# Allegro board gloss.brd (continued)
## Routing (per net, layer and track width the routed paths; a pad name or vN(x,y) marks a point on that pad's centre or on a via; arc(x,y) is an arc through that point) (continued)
MEMORY.RA9: length 273.9
  TOP w0.15: U23.22 110.67,115.61 111.47,116.41 112.34,116.41 112.58,116.16 112.58,114.14 112.47,114.03 112.47,106.97 ; v1(116.34,71.61) 111.86,71.61 111.24,72.23 107.78,72.23 106.13,73.88 106.13,75.06 106.23,75.16 106.23,77.25 106.39,77.41 109.88,77.41 110.67,76.61 U20.22 ; 112.47,106.97 115.75,106.97 v1(116.49,107.7) 117.26,107.7 118.28,106.68 118.28,91.57 117.14,90.43 115.74,90.43 115.47,90.7 110.89,90.7 110.67,90.48 U21.22 ; 112.47,106.97 112.58,106.85 112.58,101.28 112.26,100.95 111.28,100.95 110.67,101.56 U22.22 ; v1(86.46,87.01) 85.89,87.58 85.89,87.77 86.67,88.56 U17.22 86.67,90.48 86.45,90.7 81.96,90.7 80.96,91.71 80.96,93.86 81.08,93.97 81.08,95.95 86.67,101.56 U18.22 86.46,102.43 v1(86.46,103.84) ; v1(88.28,74.6) 87.03,74.6 86.67,74.95 U16.22 ; U19.22 v1(86.67,111.97) ; U5.65 v1(68.91,102.77)
  BOTTOM w0.15: v1(116.49,107.7) 116.49,98.77 116.08,98.36 116.08,90.16 116.92,89.32 116.92,84.9 116.64,84.62 116.64,72.73 116.34,72.43 v1(116.34,71.61) 116.34,64.61 113.8,62.07 76.05,62.07 71.99,66.13 71.99,66.65 72.5,67.16 93.19,67.16 93.82,67.79 93.82,69.43 91.66,71.59 91.29,71.59 v1(88.28,74.6) 89.2,75.52 89.2,85.86 88.06,87.01 v1(86.46,87.01) ; v1(86.67,111.97) 86.67,111.15 87.19,110.63 87.19,104.57 v1(86.46,103.84) 84.86,103.84 80.89,99.87 71.81,99.87 v1(68.91,102.77)
MEMORY.RA10: length 199.7
  TOP w0.15: 111.42,109.47 111.94,109.99 U23.21 ; 111.42,109.47 111.12,109.77 99.79,109.77 99.56,109.99 v1(98.75,109.99) ; 111.42,109.47 v1(111.42,107.4) 111.42,104.59 111.94,104.08 U22.21 ; U5.64 64.6,101.36 v1(62.81,101.36) ; v1(79.62,85.57) 79.39,85.57 78.1,86.85 78.1,87.93 78.42,88.25 78.42,93.86 78.31,93.97 v1(78.31,97.03) ; U18.21 v1(87.94,100.6) v1(87.94,98.5) ; v1(88.47,82.06) 88.39,82.13 86.16,82.13 84.77,80.75 84.77,78.71 85.77,77.7 87.72,77.7 87.94,77.48 U16.21 ; U20.21 v1(111.94,77.84) 110.95,77.84 110.04,78.75 110.04,80.85 111.94,82.75 U21.21 ; v1(87.95,113.6) 87.94,113.6 U19.21 ; U17.21 v1(87.94,85.97)
  BOTTOM w0.15: v1(98.75,109.99) 98.79,109.96 98.79,104.71 97.77,103.69 95.23,103.69 92.81,106.11 92.81,112.68 91.16,114.33 88.68,114.33 v1(87.95,113.6) 87.94,113.6 v1(87.94,100.6) ; 78.31,98.38 65.79,98.38 v1(62.81,101.36) ; 78.31,98.38 v1(78.31,97.03) ; 78.31,98.38 78.6,98.67 86.96,98.67 87.13,98.5 v1(87.94,98.5) ; v1(111.42,107.4) 111.42,103.35 114.25,100.52 114.25,92.81 114.52,92.54 114.52,85.01 113.71,84.2 113.71,72.03 113.31,71.63 112.78,71.63 111.98,72.43 111.98,73.35 111.21,74.12 111.21,77.11 v1(111.94,77.84) ; v1(88.47,82.06) 87.94,82.58 v1(87.94,85.97) 80.03,85.97 v1(79.62,85.57)
MEMORY.RA11: length 171.4
  TOP w0.15: U22.20 v1(113.22,98.26) ; U21.20 113.22,88.1 v1(113.78,87.53) 113.78,80.87 113.85,80.81 113.85,78.36 113.22,77.72 U20.20 ; U17.20 89.22,86.96 92.49,83.69 v1(92.49,82.43) ; U18.20 v1(89.22,103.69) 89.23,103.7 91.89,103.7 92.39,103.21 92.39,100.26 94.36,98.28 94.36,82.74 v1(94.67,82.43) 94.67,76.18 91.62,73.14 90.48,73.14 89.22,74.41 U16.20 ; U19.20 v1(89.22,112.14) 90.62,110.73 103.25,110.73 104.06,111.53 109.04,111.53 110.04,112.54 110.04,116.23 110.81,117 112.71,117 113.22,116.5 U23.20 v1(113.22,108.43) ; U5.63 v1(67.05,100.23)
  BOTTOM w0.15: v1(113.78,87.53) 113.78,97.69 v1(113.22,98.26) 110.69,100.79 110.69,107.8 111.33,108.43 v1(113.22,108.43) ; v1(67.05,100.23) 67.71,99.57 88.07,99.57 89.22,100.71 v1(89.22,103.69) v1(89.22,112.14) ; v1(92.49,82.43) v1(94.67,82.43)
MEMORY.RA12: length 193.7
  TOP w0.15: U22.19 v1(114.48,103.84) ; U5.62 66.86,98.96 67.88,99.98 v1(67.88,101.06) ; 118.28,85.57 118.28,75.87 117.01,74.6 v1(115.74,74.6) 114.84,74.6 114.48,74.95 U20.19 ; 118.28,85.57 118.88,86.17 118.88,107.12 115.58,110.43 v1(114.48,110.43) U23.19 ; 118.28,85.57 116.23,85.57 114.7,87.1 114.7,87.73 114.48,87.95 U21.19 ; 92.28,87.17 93.55,85.9 93.55,78.7 v1(93.01,78.16) ; 92.28,87.17 91.97,86.87 90.88,86.87 90.48,87.27 U17.19 ; 92.28,87.17 92.39,87.28 92.39,96.25 90.48,98.15 v1(90.48,99.23) U18.19 ; U19.19 v1(90.48,113.6) ; U16.19 90.48,75.56 89.88,74.95 89.88,74.79 v1(90.81,73.87)
  BOTTOM w0.15: v1(90.48,113.6) v1(90.48,99.23) 66.81,99.23 66.02,100.03 66.02,100.55 66.53,101.06 v1(67.88,101.06) ; v1(93.01,78.16) 92,79.17 91.32,79.17 90.81,78.66 v1(90.81,73.87) 91.62,73.87 95.62,69.87 95.62,65.5 98.42,62.71 113.99,62.71 115,63.73 115,73.87 v1(115.74,74.6) ; v1(114.48,103.84) v1(114.48,110.43)
MEMORY.RA13: length 165
  TOP w0.15: U21.18 115.75,87.64 v1(116.19,87.2) ; v1(108.73,112.27) 104.34,112.27 103.58,113.03 103.58,114.03 103.69,114.14 103.69,116.16 103.45,116.41 92.56,116.41 91.75,115.61 U19.18 v1(91.75,112.66) ; U16.18 91.75,76.61 92.56,77.41 93.34,77.41 93.84,77.91 93.84,96.12 v1(91.97,97.99) 91.75,98.21 U18.18 91.75,102.61 90.95,103.41 90.08,103.41 89.75,103.08 v1(89.75,91.14) 91.12,91.14 91.75,90.5 U17.18 ; v1(68.76,92.6) 68.76,95.28 66.35,97.69 U5.61 ; U23.18 v1(115.75,111.84) ; U22.18 115.68,102.14 v1(115.68,100.6) ; U20.18 v1(115.75,78.14)
  BOTTOM w0.15: v1(91.97,97.99) 91.97,112.44 v1(91.75,112.66) ; v1(68.76,92.6) 88.29,92.6 v1(89.75,91.14) ; v1(115.75,78.14) 116.19,78.57 v1(116.19,87.2) 116.19,88.02 115.78,88.43 115.78,100.5 v1(115.68,100.6) 115.75,100.68 v1(115.75,111.84) 115.33,112.27 v1(108.73,112.27)
MEMORY.RA14: length 221.6
  TOP w0.15: v1(117.55,82.23) 116.73,82.23 115.75,81.25 U21.15 ; v1(87.04,83.52) 91.36,83.52 91.75,83.12 U17.15 ; U18.15 91.75,95.69 v1(91.22,96.23) ; U20.15 115.75,64.57 115.45,64.27 ; U19.15 91.75,106.86 v1(91.22,107.4) ; U16.15 v1(91.75,69.66) 92.49,70.39 100.27,70.39 101.03,69.63 101.03,67.97 101.15,67.85 101.15,65.84 100.91,65.59 v1(97.02,65.59) ; U22.15 115.75,94.05 116.48,94.77 v1(117.55,94.77) 117.55,95.59 117.84,95.89 117.84,103.03 115.75,105.11 U23.15 ; v1(117.07,63.67) 116.05,63.67 115.45,64.27 ; 115.45,64.27 v1(112.11,64.27) ; U5.60 64.94,96.23 v1(66.69,96.23) 68.03,94.89 v1(68.03,89.17)
  BOTTOM w0.15: v1(91.22,107.4) v1(91.22,96.23) v1(66.69,96.23) ; v1(112.11,64.27) 111.3,64.27 110.82,63.8 98.82,63.8 v1(97.02,65.59) ; v1(68.03,89.17) 68.03,88.36 68.43,87.96 68.43,71.57 72.24,67.76 92.82,67.76 93.22,68.15 93.22,69.02 92.59,69.66 v1(91.75,69.66) 90.86,68.76 87.38,68.76 86.87,69.27 86.87,77.08 85.94,78.01 85.94,82.42 v1(87.04,83.52) ; v1(117.07,63.67) 117.07,81.75 v1(117.55,82.23) v1(117.55,94.77)
MEMORY.RA15: length 218.2
  TOP w0.15: v1(67.29,91.57) 67.29,92.93 66.34,93.88 U5.58 ; v1(91.02,81.4) 90.48,80.86 U17.14 ; U16.14 90.48,65.59 ; 90.48,65.59 95.61,65.59 v1(96.94,66.93) ; 90.48,65.59 86.18,65.59 86.04,65.73 86.04,68 84.04,70 79.97,70 79.58,69.6 79.58,67.97 79.69,67.85 79.69,65.81 79.18,65.3 72.56,65.3 71.54,66.31 v1(71.54,69.52) ; U20.14 114.27,66.57 v1(114.27,65.16) ; U23.14 114.48,105.11 113.75,104.38 113.75,103.38 113.85,103.28 113.85,101.09 117.55,97.4 117.55,96.31 115.8,94.56 v1(114.99,94.56) 114.99,93.29 U22.14 ; U19.14 90.48,104.52 90.58,104.42 92.4,104.42 93.55,103.28 v1(93.55,100.6) ; v1(115,81.47) 114.48,80.95 U21.14 ; U18.14 v1(90.48,94.76)
  BOTTOM w0.15: v1(91.02,81.4) 91.63,81.4 97.68,75.35 97.68,66.93 ; 71.66,91.57 84.38,91.57 85.54,90.41 91.63,90.41 96.94,95.71 96.94,96.93 96.55,97.33 95.97,97.33 92.31,93.67 88.36,93.67 87.96,94.06 87.96,94.73 88.72,95.49 89.75,95.49 v1(90.48,94.76) 91.26,94.76 93.55,97.04 v1(93.55,100.6) ; 71.66,91.57 71.66,69.65 v1(71.54,69.52) ; 71.66,91.57 v1(67.29,91.57) ; 97.68,66.93 100.51,64.09 110.29,64.09 111.35,65.16 v1(114.27,65.16) 114.27,80.74 v1(115,81.47) 115,94.55 v1(114.99,94.56) ; 97.68,66.93 v1(96.94,66.93)
MEMORY.RCS0: length 55.7
  TOP w0.15: U5.51 60.66,84.96 69.94,75.69 69.94,67.49 72.73,64.69 79.5,64.69 80.33,65.52 U16.6 v1(80.33,69.27) ; U17.6 v1(80.33,81.4)
  BOTTOM w0.15: v1(80.33,69.27) 78.91,69.27 78.02,70.15 78.02,79.09 v1(80.33,81.4)
MEMORY.RCS1: length 77.8
  TOP w0.15: U19.6 80.33,108.16 78.52,109.97 78.52,114.06 78.42,114.16 78.42,117.3 77.42,118.3 73.71,118.3 68.63,113.22 68.63,105.46 67.84,104.67 63.01,104.67 v1(61.64,103.31) ; U5.50 59.39,88.48 v1(61.64,90.73) ; v1(80.33,94.4) U18.6
  BOTTOM w0.15: v1(61.64,103.31) 61.64,94.91 ; 61.64,94.91 66,94.91 66.52,94.4 v1(80.33,94.4) ; 61.64,94.91 v1(61.64,90.73)
MEMORY.RCS2: length 122.1
  TOP w0.15: U20.6 104.33,67.16 105.12,67.97 108.53,67.97 108.77,67.72 108.77,65.83 109.04,65.56 109.94,65.56 110.33,65.16 110.33,64.45 108.68,62.8 v1(94.89,62.8) 74.05,62.8 69.64,67.22 69.64,75.47 62.14,82.97 60.79,82.97 58.12,85.63 U5.49 ; U21.6 104.33,79.39 103.53,78.59 98.75,78.59 98.61,78.73 98.61,80.86 98.5,80.97 98.5,82.64 v1(96.64,84.5)
  BOTTOM w0.15: v1(94.89,62.8) 94.89,63.61 95.29,64.01 95.29,69.69 92.49,72.49 91.09,72.49 90.08,73.5 90.08,82.91 91.66,84.5 v1(96.64,84.5)
MEMORY.RCS3: length 176.1
  TOP w0.15: v1(117.8,64.84) 117.8,52.61 115.64,50.45 71.14,50.45 68.73,52.87 68.73,74.27 61.23,81.77 60.74,81.77 56.85,85.66 U5.48 ; U23.6 v1(104.33,108.22) ; U22.6 v1(104.33,94.4) ; v1(111.41,95.68) 111.41,93.94 111.31,93.84 111.31,91.77 111.92,91.16 v1(116.81,91.16)
  BOTTOM w0.15: v1(111.41,95.68) 104.33,95.68 ; 104.33,95.68 v1(104.33,94.4) ; 104.33,95.68 104.05,95.96 104.05,98.67 105.88,100.51 105.88,107.72 105.38,108.22 v1(104.33,108.22) ; v1(117.8,64.84) 117.8,65.65 117.47,65.99 117.47,76.28 118.28,77.09 118.28,95.11 117.88,95.51 117.21,95.51 116.81,95.11 v1(116.81,91.16)
MEMORY.RD0: length 176.3
  TOP w0.15: v1(104.4,86.44) 103.58,87.26 103.58,88.03 103.69,88.14 103.69,90.19 103.18,90.7 100.47,90.7 100.04,91.14 v1(99.23,91.14) ; v1(88.69,94.4) 88.69,91.92 88.37,91.59 82.4,91.59 81.59,92.39 U18.7 81.59,94.9 87.19,100.5 87.19,101.03 87.31,101.14 87.31,104.06 86.8,104.57 85,104.57 84.77,104.8 84.77,106.84 84.87,106.94 84.87,114.06 84.77,114.16 84.77,116.28 84.87,116.38 84.87,117.59 83.85,118.6 56.84,118.6 55.58,117.34 U5.81 ; U20.7 v1(105.59,65.16) 104.86,64.43 82.48,64.43 81.59,65.32 U16.7 ; U22.7 v1(105.59,94.4)
  BOTTOM w0.15: v1(99.23,91.14) 99.23,91.95 99.01,92.17 99.01,101.3 97.36,102.95 96.61,102.95 94.58,100.92 94.58,97.58 91.02,94.02 89.88,94.02 89.51,94.4 v1(88.69,94.4) ; v1(105.59,65.16) 103.59,67.16 103.59,75.27 110.95,82.63 110.95,84.88 110.16,85.67 105.16,85.67 v1(104.4,86.44) 105.59,87.63 v1(105.59,94.4)
MEMORY.RD1: length 143.7
  TOP w0.15: v1(75.78,95.49) 75.78,86.16 v1(75.98,85.96) ; v1(81.81,68.97) 82.51,68.27 85.19,68.27 85.41,68.05 U16.10 85.41,65.5 86.04,64.86 102.78,64.86 103.69,65.77 103.69,67.87 104.08,68.27 109.19,68.27 109.41,68.05 U20.10 ; U22.10 109.41,94.65 107.75,96.3 v1(96.21,96.3) ; U18.10 85.41,95.49 v1(85.41,95.49) ; v1(62.67,96.96) 54.31,105.32 U5.82
  BOTTOM w0.15: v1(75.98,85.96) 75.98,77.39 75.55,76.95 75.55,71.96 78.97,68.53 81.38,68.53 v1(81.81,68.97) ; v1(96.21,96.3) 93.28,93.36 88.17,93.36 87.41,94.13 87.41,94.7 86.62,95.49 v1(85.41,95.49) v1(75.78,95.49) 64.14,95.49 v1(62.67,96.96)
MEMORY.RD2: length 199.3
  TOP w0.15: U22.23 109.41,99.73 v1(109.6,99.53) ; U18.23 85.41,103.48 85.19,103.7 83.28,103.7 82.23,104.75 82.23,106.84 82.13,106.94 82.13,109.64 84.03,111.54 v1(84.03,113.43) ; U5.83 v1(53.04,112.04) ; v1(112.98,72.66) 110.28,72.66 v1(109.41,73.54) U20.23 ; v1(104.69,73.07) 103.88,73.07 103.55,72.74 98.37,72.74 98.17,72.54 86.29,72.54 85.41,73.42 U16.23 ; v1(85.92,113.43) 85.92,116.06 86.27,116.41 86.97,116.41 87.41,116.84 v1(104.33,116.84)
  BOTTOM w0.15: v1(85.92,113.43) v1(84.03,113.43) ; v1(109.41,73.54) 108.94,73.07 v1(104.69,73.07) ; v1(53.04,112.04) 46.93,112.04 45.66,113.31 45.66,114.41 49.98,118.73 102.44,118.73 v1(104.33,116.84) 103.59,116.11 103.59,110.27 104.61,109.26 107.7,109.26 109.6,107.35 v1(109.6,99.53) 110.41,99.53 112.98,96.97 v1(112.98,72.66)
MEMORY.RD3: length 177.2
  TOP w0.15: v1(111.96,74.47) 113.03,73.4 115.67,73.4 117.07,72 117.07,71.28 116.56,70.77 106.86,70.77 105.3,72.34 ; U22.26 105.59,99.51 v1(105.79,99.31) 102.94,99.31 101.15,101.1 101.15,103.56 99.88,104.83 99.88,106.78 99.26,107.4 v1(98.05,107.4) ; v1(80.31,103.84) 81.24,103.84 81.59,103.48 U18.26 ; 105.3,72.34 105.59,72.63 U20.26 ; 105.3,72.34 103.39,72.34 103.29,72.44 100.17,72.44 99.97,72.24 84.13,72.24 81.59,74.78 U16.26 ; U5.84 v1(51.77,104.78)
  BOTTOM w0.15: 80.05,105.08 79.75,104.78 v1(51.77,104.78) ; 80.05,105.08 80.31,104.82 v1(80.31,103.84) ; 80.05,105.08 80.05,111.59 83.1,114.64 91.33,114.64 93.11,112.86 93.11,106.28 95.4,104 97.55,104 98.05,104.5 v1(98.05,107.4) ; v1(111.96,74.47) 112.68,75.18 112.68,96.11 110.11,98.67 106.43,98.67 v1(105.79,99.31)
MEMORY.RD4: length 171.3
  TOP w0.15: U21.7 v1(105.59,81.4) ; v1(105.15,107.4) 105.59,106.95 U23.7 ; U5.1 v1(50.5,113.07) ; U17.7 81.59,81.05 83.34,82.79 v1(91.02,82.79) ; v1(79.16,117.57) 79.16,116.76 79.69,116.23 79.69,114.19 81.59,112.29 U19.7
  BOTTOM w0.15: 79.16,118.3 v1(79.16,117.57) ; 79.16,118.3 79.04,118.43 50.15,118.43 45.96,114.23 45.96,113.47 46.35,113.07 v1(50.5,113.07) ; 79.16,118.3 102.13,118.3 103.27,117.16 103.27,107.42 103.59,107.1 ; 103.59,107.1 103.89,107.4 v1(105.15,107.4) ; 103.59,107.1 103.59,84.37 105.59,82.37 v1(105.59,81.4) 105.59,79.59 103.27,77.27 103.27,69.36 101.36,67.46 98.74,67.46 97.98,68.22 97.98,75.83 v1(91.02,82.79)
MEMORY.RD5: length 265.8
  TOP w0.15: 94.13,109.26 v1(94.13,109.99) ; 94.13,109.26 107.75,109.26 109.41,107.61 U23.10 ; 94.13,109.26 87.62,109.26 85.41,107.05 U19.10 ; U5.2 v1(49.23,109.47) ; U21.10 109.41,78.52 108.59,77.7 99.13,77.7 98.61,77.19 98.61,75.28 98.37,75.03 v1(96.94,75.03) ; U17.10 85.41,79.11 86.38,78.14 v1(91.84,78.14) ; v1(113.62,63.44) v1(113.62,61.33)
  BOTTOM w0.15: v1(94.13,109.99) 94.13,105.69 95.53,104.3 97.36,104.3 97.75,104.69 97.75,106.14 97.32,106.58 97.32,111.86 98.05,112.59 98.05,114.35 97.17,115.23 57.22,115.23 56.08,114.09 56.08,110.31 54.93,109.17 50.74,109.17 ; 96.21,75.03 v1(96.94,75.03) ; 96.21,75.03 94.95,75.03 v1(91.84,78.14) ; 96.21,75.03 96.21,65.35 98.11,63.44 v1(113.62,63.44) ; 50.74,109.17 50.44,109.47 v1(49.23,109.47) ; 50.74,109.17 50.74,102.97 59.53,94.17 59.53,79.19 62.83,75.89 65.09,75.89 67.38,73.61 67.38,70.22 76.27,61.33 v1(113.62,61.33)
MEMORY.RD6: length 147.1
  TOP w0.15: U5.3 v1(47.96,113.81) ; U23.23 109.41,116.53 107.63,118.3 87.26,118.3 v1(86.16,117.2) 85.41,116.45 U19.23 ; U17.23 85.41,86.91 86.04,86.28 86.8,86.28 87.31,86.79 87.31,90.27 87.45,90.41 90.89,90.41 91.22,90.08 v1(91.22,87.6) ; U21.23 109.41,90.5 108.9,91 101.92,91 101.15,91.78 101.15,94.63 v1(100.22,95.56)
  BOTTOM w0.15: v1(91.22,87.6) 96.79,87.6 99.96,90.78 99.96,92.53 99.48,93.01 99.48,95.56 ; v1(47.96,113.81) 49.99,115.83 84.79,115.83 v1(86.16,117.2) 95.67,117.2 99.48,113.39 99.48,95.56 ; 99.48,95.56 v1(100.22,95.56)
MEMORY.RD7: length 167.5
  TOP w0.15: v1(101.81,117.57) 104.71,117.57 105.59,116.68 U23.26 ; U17.26 v1(81.59,87.57) ; U5.4 v1(46.69,113.81) ; v1(102.75,82.64) 103.83,82.64 105.59,84.41 U21.26 ; U19.26 v1(81.59,116.84)
  BOTTOM w0.15: v1(46.69,113.81) 49.72,116.84 v1(81.59,116.84) 82.69,117.93 100.64,117.93 101,117.57 v1(101.81,117.57) 101.81,109.99 102.41,109.39 102.41,104.11 102.11,103.81 102.11,97.93 102.52,97.52 102.52,91.46 102.11,91.06 102.11,83.28 v1(102.75,82.64) 102.75,80.14 101.8,79.19 101.8,73.51 102.74,72.57 102.74,69.28 101.21,67.76 98.91,67.76 98.28,68.39 98.28,76.67 95.21,79.74 95.21,81.14 97.38,83.3 97.38,84.89 96.74,85.53 90.9,85.53 88.43,88 82.03,88 v1(81.59,87.57)
MEMORY.RWE: length 210.6
  TOP w0.15: 110.95,96.63 110.67,96.36 U22.11 ; 110.95,96.63 110.95,100.17 110.04,101.08 110.04,103.3 110.16,103.41 110.16,104 ; 110.95,96.63 v1(116.81,96.63) ; 110.16,104 110.67,104.52 U23.11 ; 110.16,104 109.86,104.3 104.21,104.3 103.69,104.81 103.69,106.9 101.8,108.79 90.31,108.79 88.48,106.97 ; 88.48,106.97 88.58,106.87 88.58,104.72 88.48,104.62 88.48,102.33 88.68,102.14 88.68,96.91 v1(86.38,94.61) 86.38,93.08 U18.11 ; 88.48,106.97 87.47,106.97 86.67,106.17 U19.11 ; U16.11 86.67,68.39 v1(87.77,69.49) ; v1(118.2,73.7) 117.37,73.7 ; 117.37,73.7 114.09,73.7 112.58,75.21 112.58,77.3 112.69,77.41 112.69,78.17 112.3,78.57 111.58,78.57 110.67,79.47 U21.11 ; 117.37,73.7 117.37,71.14 114.2,67.97 111.47,67.97 110.67,67.16 U20.11 ; U5.56 v1(62.81,91.34) ; v1(86.67,81.4) U17.11
  BOTTOM w0.15: 65.96,91.34 67.96,93.34 85.1,93.34 v1(86.38,94.61) ; 65.96,91.34 65.96,83.2 67.98,81.18 67.98,71.52 72.04,67.46 93.01,67.46 93.52,67.97 93.52,69.25 92.38,70.39 87.77,70.39 ; 65.96,91.34 v1(62.81,91.34) ; v1(116.81,96.63) 117.62,96.63 118.7,95.55 118.7,75.01 118.2,74.51 v1(118.2,73.7) ; 87.77,70.39 v1(87.77,69.49) ; 87.77,70.39 87.47,70.69 87.47,80.6 v1(86.67,81.4)
MRD: length 48.5
  BOTTOM w0.15: U2.9 43.1,68.92 43.1,57.48 38.79,53.16 13.53,53.16 13.17,53.52 J1.46
MWR: length 53.8
  BOTTOM w0.15: U2.10 42.14,70.5 42.14,61.61 38.52,58 37.66,58 37.61,58.05 17.63,58.05 16.95,57.37 11.91,57.37 10.77,56.23 10.77,52.29 J1.45
N00036_DATA_DAAMP: length 46.6
  TOP w0.15: U8.8 83.66,42.67 ; 83.66,42.67 84.5,43.51 v1(84.5,45.41) U10.5 ; 83.66,42.67 83.66,38.86 ; L4.2 93.88,30.77 85.78,38.86 83.66,38.86 ; 83.66,38.86 U8.5
  BOTTOM w0.15: R7.1 89.66,36 91.95,33.71 91.95,31.93 L4.2 ; R6.1 89.72,38.5 90.05,38.83 90.05,43.75 88.4,45.41 v1(84.5,45.41)
N00036_DATA_DAAMP1: length 44.1
  TOP w0.15: 83.97,22.75 U11.8 ; 83.97,22.75 v1(83.97,23.68) 83.97,24.71 84.73,25.48 U13.5 ; 83.97,22.75 83.97,19.24 ; 83.97,19.24 86.38,19.24 88.9,16.73 93.83,16.73 94.97,15.59 94.97,11.17 L6.2 ; 83.97,19.24 83.66,18.94 U11.5
  BOTTOM w0.15: 89.67,18.58 89.67,16.7 89.06,16.08 R9.1 ; 89.67,18.58 R8.1 ; 89.67,18.58 89.67,23.04 89.04,23.68 v1(83.97,23.68)
N00038_DATA_DAAMP: length 19.9
  TOP w0.15: v1(85.89,37.59) U8.4 v1(79.11,37.59)
  BOTTOM w0.15: v1(79.11,37.59) 78.53,37.02 77.62,37.02 77.5,37.14 C8.1 ; v1(85.89,37.59) 86.21,37.27 89.38,37.27 93.88,32.77 L3.2
N00038_DATA_DAAMP1: length 22.3
  TOP w0.15: L5.2 87.9,12.58 v1(84.1,16.38) 84.1,17.19 83.62,17.67 U11.4
  BOTTOM w0.15: v1(84.1,16.38) 78.29,16.38 77.5,17.17 C11.1
N00044_DATA_DAAMP: length 6.1
  TOP w0.15: U10.1 92.56,41.59 94.22,39.93 U9.2
N00044_DATA_DAAMP1: length 6.1
  TOP w0.15: U13.1 92.56,21.67 94.22,20.01 96.43,20.01
N00060_DATA_DAAMP: length 43.6
  TOP w0.15: v1(98.5,29.02) 79.53,29.02 77.75,30.8 77.75,37.34 80.54,40.14 U8.6
  BOTTOM w0.15: U9.3 v1(98.5,29.02)
N00060_DATA_DAAMP1: length 25.7
  TOP w0.15: v1(92.38,15.7) 87.99,15.7 85.38,18.31 81.05,18.31 80.82,18.54 80.82,19.6 81.44,20.21 U11.6
  BOTTOM w0.15: v1(92.38,15.7) 92.38,14.88 93.44,13.83 94.42,13.83 98.5,17.91 U12.3
N282866_DATA_DAAMP: length 4
  TOP w0.15: U10.8 86.03,40.38 v1(86.19,40.21)
  BOTTOM w0.15: R6.2 86.28,38.5 86.19,38.59 v1(86.19,40.21)
N282866_DATA_DAAMP1: length 3.6
  TOP w0.15: U13.8 86.03,20.59 v1(86.33,20.29)
  BOTTOM w0.15: v1(86.33,20.29) 86.33,19.2 86.94,18.58 R8.2
N282912_DATA_DAAMP: length 12.6
  TOP w0.15: U10.2 89.25,42.87 v1(89.02,42.63)
  BOTTOM w0.15: v1(89.02,42.63) 87.53,42.63 84.86,39.96 84.86,37.4 86.26,36 R7.2
N282912_DATA_DAAMP1: length 12
  TOP w0.15: U13.2 v1(88.72,22.94)
  BOTTOM w0.15: v1(88.72,22.94) 87.88,22.94 85.59,20.66 85.59,16.77 86.28,16.08 R9.2
NCS: length 18.9
  TOP w0.15: U5.11 v1(37.8,118.05)
  BOTTOM w0.15: v1(37.8,118.05) 29,109.25 U7.4
OE: length 19.3
  TOP w0.15: U5.32 35.27,88.8 34.67,89.4 34.67,91.64 30.86,95.45 v1(29.33,95.45)
  BOTTOM w0.15: v1(29.33,95.45) 27.77,97.01 27.77,101.36 U7.3
OUTA: length 16.6
  TOP w0.15: U9.6 101.8,44.07 102.57,43.29 102.57,39.37 98.2,35 L1.1
OUTB: length 18
  BOTTOM w0.15: L2.1 94,23.4 97.3,26.7 99.24,26.7 100.57,25.38 U12.6
Q0: length 8.5
  TOP w0.15: U6.18 73.5,60.17 73.67,60 R1.1
Q1: length 8.4
  TOP w0.15: R2.1 73.55,57.5 73.41,57.63 U6.16
Q2: length 8.4
  TOP w0.15: U6.14 73.41,55.09 73.51,55 R3.1
Q3: length 8.4
  TOP w0.15: U6.12 73.41,52.55 73.47,52.5 R4.1
RDY: length 49.9
  BOTTOM w0.15: J1.50 10.17,61.77 10.17,51.36 11.67,49.86 12.4,49.86 13.39,50.86 13.39,51.5 12.6,52.29 11.86,52.29 11.07,53.09 11.07,54.02 11.83,54.79 21.59,54.79 22.34,54.04 U2.23
RESET: length 54.8
  TOP w0.15: v1(24.86,88.54) 24.86,102.9 32.36,110.39 U5.15
  BOTTOM w0.15: J1.53 15.24,71.3 19.27,75.33 19.27,85.62 22.19,88.54 v1(24.86,88.54)
SEL: length 40.9
  TOP w0.15: U5.13 v1(38.34,112.93)
  BOTTOM w0.15: v1(38.34,112.93) 39.17,112.93 41.07,111.03 41.07,88.3 39.55,86.78 39.55,78.08 U2.14
V+12: length 185.5
  TOP w0.4: U12.7 96.81,26.69 v1(90.97,26.69) U13.4 ; 94.05,47.01 96.41,47.01 U9.7 ; 94.05,47.01 v1(94.05,45.41) ; 94.05,47.01 91.98,47.01 90.97,46.01 U10.4 ; v1(66.4,73.11) v1(30.99,73.11) ; J1.64 J1.63
  BOTTOM w0.4: J1.63 18.37,96.7 26.51,88.56 26.51,76.16 29.56,73.11 v1(30.99,73.11) ; v1(66.4,73.11) 66.4,59.21 79.09,46.51 92.95,46.51 v1(94.05,45.41) 94.05,37.8 95.35,36.5 95.35,29.54 94.46,28.65 91.28,28.65 ; C12.1 90.72,13.58 90.97,13.83 v1(90.97,26.69) 90.97,28.35 91.28,28.65 ; 91.28,28.65 91.28,32.99 90.77,33.5 C9.1
VCLKA: length 82
  TOP w0.2: 67.83,46.42 67.83,73.68 60.97,80.54 44.02,80.54 39.07,85.49 U5.34 ; 67.83,46.42 67.83,34.59 68.63,33.78 U14.11 ; 67.83,46.42 72.24,46.42 72.84,45.83 U8.11
VCLKC: length 100.8
  TOP w0.2: v1(67.83,29.51) 67.83,23.36 ; 67.83,23.36 73.94,23.36 74.17,23.6 74.17,25.29 U11.11 ; 67.83,23.36 67.82,23.35 67.82,14.47 68.44,13.86 U15.11
  BOTTOM w0.2: v1(67.83,29.51) 65.69,31.64 65.69,67.2 58.69,74.21 58.69,85.3 50.49,93.5 R5.2
VD0: length 88.6
  TOP w0.15: v1(53.43,82.17) 48.85,82.17 45.42,85.59 U5.39 ; U15.2 v1(58.05,24.02) ; U6.2 v1(58.08,61.45) ; U14.2 v1(58.08,43.95)
  BOTTOM w0.15: R13.2 57.75,30 58.05,29.7 ; 58.05,29.7 58.08,29.73 v1(58.08,43.95) v1(58.08,61.45) 53.43,66.1 v1(53.43,82.17) ; 58.05,29.7 v1(58.05,24.02)
VD1: length 98.4
  TOP w0.15: U15.3 v1(57.72,22.75) ; v1(51.33,83.4) 48.47,83.4 46.69,85.18 U5.40 ; 54.78,42.38 55.08,42.67 U14.3 ; 54.78,42.38 v1(54.78,27) ; 54.78,42.38 48,49.15 48,57.67 v1(51.33,61.01) 52.17,60.17 U6.3
  BOTTOM w0.15: v1(57.72,22.75) 54.78,25.7 v1(54.78,27) R17.2 ; v1(51.33,61.01) v1(51.33,83.4)
VD2: length 116.3
  TOP w0.15: v1(47.96,85.21) U5.41 ; U15.4 57.84,21.48 57.21,20.85 57.21,20.08 57.72,19.57 61.07,19.57 61.2,19.45 61.2,18.5 61,18.3 52.98,18.3 52.39,17.71 51.47,17.71 49.82,19.36 49.82,22.77 v1(51.05,24) 53.07,24 56.38,27.3 v1(56.38,40.57) 57.21,41.41 U14.4 ; v1(56.38,58.91) U6.4
  BOTTOM w0.15: v1(47.96,85.21) 47.96,57.68 51.01,54.64 56.38,54.64 ; 56.38,54.64 v1(56.38,40.57) ; 56.38,54.64 v1(56.38,58.91) ; R12.2 v1(51.05,24)
VD3: length 98.8
  TOP w0.15: 61.99,39.84 61.7,40.14 U14.5 ; 61.99,39.84 62.86,40.7 62.86,46.79 56.38,53.27 56.38,57.63 ; 61.99,39.84 61.99,21.01 61.2,20.21 U15.5 58.27,20.21 v1(58.04,20.45) ; v1(49.23,85.21) U5.42 ; 56.38,57.63 U6.5 ; 56.38,57.63 v1(49.23,57.63)
  BOTTOM w0.15: R16.2 57.49,21 v1(58.04,20.45) ; v1(49.23,57.63) v1(49.23,85.21)
VD4: length 93.9
  TOP w0.15: U6.6 v1(57.21,56.37) ; U5.43 v1(50.5,85.21) ; v1(51.45,18.94) 56.81,18.94 ; 56.81,18.94 56.81,38.47 v1(57.21,38.86) U14.6 ; 56.81,18.94 U15.6
  BOTTOM w0.15: v1(51.45,18.94) 50.51,18 R11.2 ; v1(50.5,85.21) 50.5,60.65 51.01,60.14 56.41,60.14 57.21,59.34 v1(57.21,56.37) v1(57.21,38.86)
VD5: length 122.5
  TOP w0.15: U5.44 v1(51.77,90.78) ; U14.7 61.17,37.59 61.2,37.58 61.2,28.28 v1(61.16,28.25) ; v1(53.89,15) 56.56,17.67 U15.7 61.23,17.67 62.03,18.47 v1(62.03,19.38) 64.19,21.55 v1(64.19,50.22) 64.19,55.08 64.17,55.09 U6.7
  BOTTOM w0.15: R15.2 v1(53.89,15) ; v1(64.19,50.22) 63.23,51.19 63.23,63.31 57.46,69.08 57.46,85.09 v1(51.77,90.78) ; v1(61.16,28.25) 61.16,20.25 v1(62.03,19.38)
VD6: length 98.5
  TOP w0.15: U15.8 v1(58.05,16.4) ; U14.8 58.48,36.33 58.08,35.93 58.08,30.71 v1(58.92,29.88) ; U6.8 v1(58.92,53.83) ; U5.45 v1(53.04,83.83)
  BOTTOM w0.15: R10.2 53.65,12 v1(58.05,16.4) 58.92,17.27 v1(58.92,29.88) v1(58.92,53.83) 58.92,63.34 55.43,66.82 55.43,81.44 v1(53.04,83.83)
VD7: length 104.7
  TOP w0.15: U15.9 v1(63.26,15.13) ; U14.9 58.51,35.05 58.48,35.03 58.48,32.45 59.37,31.56 v1(60.33,31.56) ; U5.46 v1(54.31,85.06) ; U6.9 v1(61.2,52.55)
  BOTTOM w0.15: R14.2 57.13,9 v1(63.26,15.13) 63.26,29.49 61.2,31.56 ; v1(54.31,85.06) 56.66,82.71 56.66,67.88 61.2,63.34 v1(61.2,52.55) 61.2,31.56 ; 61.2,31.56 v1(60.33,31.56)
VREF: length 26.2
  TOP w0.15: R18.1 104.08,10 L5.1
  BOTTOM w0.15: L3.1 102.89,31.11 102.89,13.97 L5.1
WAIT: length 42.7
  TOP w0.15: v1(32.44,85.7) 33.99,87.25 U5.33
  BOTTOM w0.15: J1.51 12.88,67.03 27.87,67.03 32.44,71.6 v1(32.44,85.7)
WSTAT: length 53.4
  TOP w0.15: U6.11 70.81,51.28 69.04,53.06 69.04,74.87 61.54,82.36 60.89,82.36 57.48,85.77 57.48,88.45 61.65,92.61 U5.57
N14843: length 3.2
  BOTTOM w0.15: R16.1 C19.1
N14849: length 3.2
  BOTTOM w0.15: R12.1 C15.1
N14853: length 3.2
  BOTTOM w0.15: R17.1 C20.1
N14855: length 3.2
  BOTTOM w0.15: R13.1 C16.1
N15143: length 3.2
  BOTTOM w0.15: R14.1 C17.1
N15151: length 3.2
  BOTTOM w0.15: R10.1 C13.1
N15155: length 3.2
  BOTTOM w0.15: R15.1 C18.1
N15161: length 3.2
  BOTTOM w0.15: R11.1 C14.1
N58063: length 3.7
  TOP w0.15: U14.19 U8.12
N58118: length 3.7
  TOP w0.15: U14.18 U8.13
N58173: length 3.7
  TOP w0.15: U14.17 U8.14
N58228: length 3.7
  TOP w0.15: U14.16 U8.15
N58283: length 3.7
  TOP w0.15: U14.15 U8.16
N58338: length 3.7
  TOP w0.15: U14.14 U8.17
N58393: length 3.7
  TOP w0.15: U14.13 U8.18
N58448: length 3.7
  TOP w0.15: U14.12 U8.19
N58834: length 3.7
  TOP w0.15: U15.19 U11.12
N58889: length 3.7
  TOP w0.15: U15.18 U11.13
N58944: length 3.7
  TOP w0.15: U15.17 U11.14
N58999: length 3.7
  TOP w0.15: U15.16 U11.15
N59054: length 3.7
  TOP w0.15: U15.15 U11.16
N59109: length 3.7
  TOP w0.15: U15.14 U11.17
N59164: length 3.7
  TOP w0.15: U15.13 U11.18
N59219: length 3.7
  TOP w0.15: U15.12 U11.19
N409523: length 7.8
  TOP w0.15: U5.37 42.88,92.45 v1(43.93,93.5)
  BOTTOM w0.15: R5.1 v1(43.93,93.5)

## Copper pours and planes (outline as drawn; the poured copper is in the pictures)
GND on GND1, GND2: 21,1.41 21,9 20.41,10.41 19,11 1.41,11 1,11.41 1,108.59 1.41,109 19,109 20.41,109.59 21,111 21,118.59 21.41,119 118.59,119 119,118.59 119,1.41 118.59,1 21.41,1 ; 2 cut-outs
VCC on VCC1, VCC2: 21,1.41 21,9 20.41,10.41 19,11 1.41,11 1,11.41 1,108.59 1.41,109 19,109 20.41,109.59 21,111 21,118.59 21.41,119 118.59,119 119,118.59 119,1.41 118.59,1 21.41,1 ; 2 cut-outs
